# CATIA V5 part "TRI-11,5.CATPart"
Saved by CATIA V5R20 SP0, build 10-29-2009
Part number: _TRI-11,5
Definition: NONE
Nomenclature: _TRI-11,5
Source: Unknown
Description: PART-_TRI-11,5-DESC
Bounding box of the stored display mesh (mm): x 0 to 17.5, y -5.75 to 5.75, z -5.75 to 5.75
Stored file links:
  C:\Users\Utente\Desktop\IO LAVORO\3D X SITO CF\X SITO\PLASTICA\TRI\TRI-11,5.CATPart
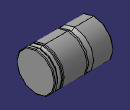
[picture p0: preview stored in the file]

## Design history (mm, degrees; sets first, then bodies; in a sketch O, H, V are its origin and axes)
Body1 "_TRI-11,5" (main body)
  Solid1: solid without history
